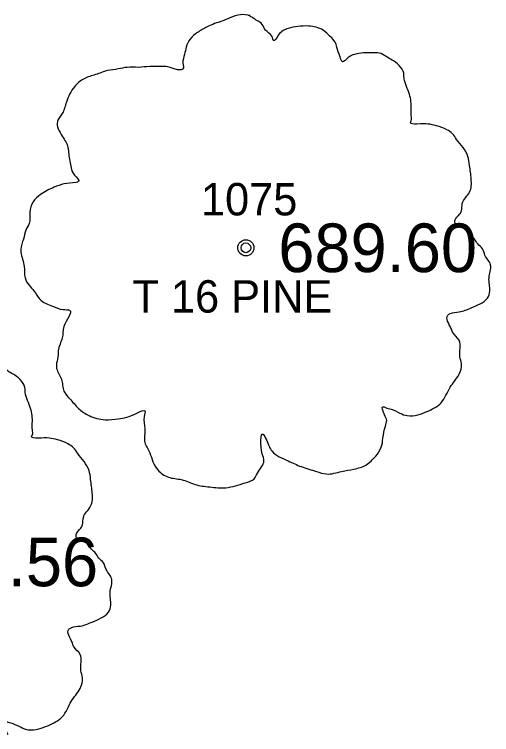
# Model space of a CAD drawing. Extents: x 1655137 to 1657928, y 1003994 to 1005407.
# Drawn here: x 1657017.34 to 1657032.07, y 1004434.92 to 1004457.14 of the extents above; entities that cross this region are included whole.
import ezdxf

# ---------------------------------------------------------------- set-up
doc = ezdxf.new("R2010")
doc.units = 0
for name, color, linetype in [('RD_EX_TX_VEG_ELEV', 7, 'Continuous'), ('RD_EX_VEG', 7, 'Continuous'), ('RD_EX_VEG_txCode', 7, 'Continuous'), ('RD_SMD_Locator', 7, 'Continuous')]:
    doc.layers.add(name, color=color, linetype=linetype)

msp = doc.modelspace()

# ---------------------------------------------------------------- linework, layer by layer
at = {"layer": 'RD_EX_VEG'}
for centre, radius in [((1657024.484, 1004449.935), 0.25), ((1657024.472, 1004449.916), 0.0001)]:
    msp.add_circle(centre, radius, dxfattribs=at)
for points in [[(1657024.616, 1004457.102), (1657024.316, 1004457.127), (1657023.992, 1004457.027), (1657023.742, 1004456.927), (1657023.517, 1004456.852), (1657023.292, 1004456.752), (1657022.992, 1004456.577), (1657022.767, 1004456.377), (1657022.642, 1004456.127), (1657022.592, 1004455.902), (1657022.542, 1004455.628), (1657022.542, 1004455.453), (1657022.417, 1004455.428), (1657022.267, 1004455.453), (1657022.017, 1004455.528), (1657021.767, 1004455.528), (1657021.518, 1004455.528), (1657021.168, 1004455.503), (1657020.818, 1004455.503), (1657020.543, 1004455.453), (1657020.218, 1004455.403), (1657019.843, 1004455.278), (1657019.493, 1004455.153), (1657019.194, 1004454.903), (1657018.944, 1004454.428), (1657018.819, 1004454.078), (1657018.669, 1004453.828), (1657018.819, 1004453.379), (1657018.994, 1004453.029), (1657019.019, 1004452.829), (1657019.094, 1004452.404), (1657019.194, 1004452.179), (1657019.319, 1004451.979), (1657019.244, 1004451.954), (1657018.869, 1004451.904), (1657018.569, 1004451.804), (1657018.144, 1004451.579), (1657017.919, 1004451.354), (1657017.819, 1004451.029), (1657017.794, 1004450.68), (1657017.694, 1004450.48), (1657017.619, 1004450.205), (1657017.594, 1004450.13), (1657017.544, 1004449.805), (1657017.644, 1004449.355), (1657017.669, 1004449.005), (1657017.794, 1004448.78), (1657017.944, 1004448.606), (1657018.119, 1004448.356), (1657018.519, 1004448.131), (1657018.844, 1004448.031), (1657019.044, 1004448.006), (1657018.869, 1004447.506), (1657018.819, 1004447.156), (1657018.694, 1004446.756), (1657018.694, 1004446.681), (1657018.644, 1004446.207), (1657018.794, 1004445.882), (1657018.869, 1004445.507), (1657019.044, 1004445.282), (1657019.319, 1004444.982), (1657019.643, 1004444.757), (1657020.143, 1004444.632), (1657020.543, 1004444.657), (1657021.118, 1004444.832), (1657021.368, 1004444.907), (1657021.343, 1004444.732), (1657021.368, 1004444.357), (1657021.368, 1004443.933), (1657021.518, 1004443.608), (1657021.618, 1004443.333), (1657021.767, 1004443.083), (1657022.092, 1004442.858), (1657022.492, 1004442.783), (1657022.917, 1004442.633), (1657023.367, 1004442.558), (1657023.867, 1004442.533), (1657024.466, 1004442.683), (1657024.741, 1004442.808), (1657024.841, 1004442.983), (1657025.041, 1004443.358), (1657024.991, 1004443.583), (1657025.016, 1004444.183), (1657025.116, 1004444.008), (1657025.291, 1004443.658), (1657025.791, 1004443.358), (1657026.191, 1004443.183), (1657026.665, 1004443.033), (1657026.965, 1004442.958), (1657027.44, 1004443.033), (1657027.815, 1004443.108), (1657028.19, 1004443.233), (1657028.49, 1004443.508), (1657028.664, 1004443.783), (1657028.714, 1004444.058), (1657028.789, 1004444.432), (1657028.839, 1004444.607)], [(1657028.839, 1004444.607), (1657028.764, 1004444.782), (1657028.714, 1004445.032), (1657028.789, 1004445.007), (1657028.964, 1004444.957), (1657029.239, 1004444.832), (1657029.464, 1004444.757), (1657029.789, 1004444.782), (1657030.064, 1004444.882), (1657030.514, 1004445.157), (1657030.789, 1004445.632), (1657031.063, 1004446.032), (1657031.138, 1004446.357), (1657031.088, 1004446.581), (1657031.063, 1004447.081), (1657030.863, 1004447.331), (1657030.813, 1004447.456), (1657030.714, 1004447.856), (1657030.789, 1004447.906), (1657031.063, 1004447.956), (1657031.438, 1004448.081), (1657031.713, 1004448.206), (1657031.938, 1004448.381), (1657032.013, 1004448.606), (1657031.988, 1004449.005), (1657032.038, 1004449.405), (1657031.963, 1004449.555), (1657031.863, 1004449.705), (1657031.788, 1004449.905), (1657031.638, 1004450.055), (1657031.538, 1004450.205), (1657031.438, 1004450.305), (1657031.313, 1004450.455), (1657031.138, 1004450.58), (1657030.988, 1004450.63), (1657030.938, 1004450.78), (1657031.088, 1004450.98), (1657031.138, 1004451.079), (1657031.163, 1004451.304), (1657031.388, 1004451.654), (1657031.438, 1004452.054), (1657031.388, 1004452.479), (1657031.338, 1004452.754), (1657031.188, 1004453.029), (1657030.988, 1004453.279), (1657030.863, 1004453.453), (1657030.689, 1004453.578), (1657030.364, 1004453.703), (1657030.114, 1004453.753), (1657029.764, 1004453.753), (1657029.564, 1004453.803), (1657029.589, 1004453.853), (1657029.589, 1004454.003), (1657029.589, 1004454.278), (1657029.514, 1004454.728), (1657029.364, 1004455.228), (1657029.364, 1004455.253), (1657029.264, 1004455.503), (1657029.039, 1004455.702), (1657028.864, 1004455.802), (1657028.664, 1004455.927), (1657028.415, 1004455.952), (1657028.115, 1004455.952), (1657027.84, 1004455.902), (1657027.64, 1004455.802), (1657027.465, 1004455.677), (1657027.39, 1004455.827), (1657027.29, 1004456.127), (1657027.24, 1004456.277), (1657027.09, 1004456.452), (1657026.865, 1004456.652), (1657026.415, 1004456.777), (1657025.791, 1004456.702), (1657025.491, 1004456.502), (1657025.341, 1004456.327), (1657025.291, 1004456.452), (1657025.091, 1004456.652), (1657024.991, 1004456.827), (1657024.816, 1004456.952), (1657024.666, 1004457.052), (1657024.566, 1004457.102)], [(1657017.145, 1004434.916), (1657017.07, 1004435.091), (1657017.02, 1004435.341), (1657017.095, 1004435.316), (1657017.27, 1004435.266), (1657017.545, 1004435.141), (1657017.77, 1004435.066), (1657018.094, 1004435.091), (1657018.369, 1004435.191), (1657018.819, 1004435.466), (1657019.094, 1004435.941), (1657019.369, 1004436.34), (1657019.444, 1004436.665), (1657019.394, 1004436.89), (1657019.369, 1004437.39), (1657019.169, 1004437.64), (1657019.119, 1004437.765), (1657019.019, 1004438.165), (1657019.094, 1004438.215), (1657019.369, 1004438.265), (1657019.744, 1004438.389), (1657020.019, 1004438.514), (1657020.244, 1004438.689), (1657020.318, 1004438.914), (1657020.294, 1004439.314), (1657020.343, 1004439.714), (1657020.269, 1004439.864), (1657020.169, 1004440.014), (1657020.094, 1004440.214), (1657019.944, 1004440.364), (1657019.844, 1004440.514), (1657019.744, 1004440.613), (1657019.619, 1004440.763), (1657019.444, 1004440.888), (1657019.294, 1004440.938), (1657019.244, 1004441.088), (1657019.394, 1004441.288), (1657019.444, 1004441.388), (1657019.469, 1004441.613), (1657019.694, 1004441.963), (1657019.744, 1004442.363), (1657019.694, 1004442.788), (1657019.644, 1004443.062), (1657019.494, 1004443.337), (1657019.294, 1004443.587), (1657019.169, 1004443.762), (1657018.994, 1004443.887), (1657018.669, 1004444.012), (1657018.419, 1004444.062), (1657018.069, 1004444.062), (1657017.87, 1004444.112), (1657017.895, 1004444.162), (1657017.895, 1004444.312), (1657017.895, 1004444.587), (1657017.82, 1004445.037), (1657017.67, 1004445.536), (1657017.67, 1004445.561), (1657017.57, 1004445.811), (1657017.345, 1004446.011), (1657017.17, 1004446.111), (1657016.97, 1004446.236), (1657016.72, 1004446.261), (1657016.42, 1004446.261), (1657016.145, 1004446.211), (1657015.945, 1004446.111), (1657015.77, 1004445.986), (1657015.695, 1004446.136), (1657015.596, 1004446.436), (1657015.546, 1004446.586), (1657015.396, 1004446.761), (1657015.171, 1004446.961), (1657014.721, 1004447.086), (1657014.096, 1004447.011), (1657013.796, 1004446.811), (1657013.646, 1004446.636), (1657013.596, 1004446.761), (1657013.396, 1004446.961), (1657013.297, 1004447.136), (1657013.122, 1004447.261), (1657012.972, 1004447.361), (1657012.872, 1004447.411)]]:
    msp.add_spline(points, degree=3, dxfattribs=at)
at = {"layer": 'RD_SMD_Locator'}
msp.add_circle((1657024.484, 1004449.935), 0.15, dxfattribs=at)

# ---------------------------------------------------------------- texts
at = {"layer": 'RD_EX_TX_VEG_ELEV'}
for s, p in [('689.60', (1657025.484, 1004449.185)), ('687.56', (1657013.79, 1004439.493))]:
    msp.add_text(s, height=1.5, dxfattribs=at).set_placement(p)
at = {"layer": 'RD_EX_VEG_txCode'}
for s, p in [('1075', (1657023.098, 1004450.935)), ('T 16 PINE', (1657020.984, 1004447.935))]:
    msp.add_text(s, height=1, dxfattribs=at).set_placement(p)

doc.saveas('drawing.dxf')
